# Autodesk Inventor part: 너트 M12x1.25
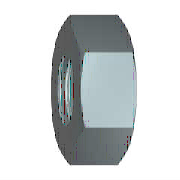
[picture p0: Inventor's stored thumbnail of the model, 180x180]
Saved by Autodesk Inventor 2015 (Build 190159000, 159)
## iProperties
IsCustomPart: 1
Created: 2012-02
Part Number: 너트 M12x1.25
Material: 강철, 연강
Description: 6각 너트
Document SubType Name: Modeling
Standard: KS B 1012
Designer: mduedu
Standards Organization: KS
Language: ko-KR
Size Designation: M12x1.25
Categories: <MemberInstance><Categories><Category DisplayName="조임쇠" InternalName="e4da775c-781d-43d5-af7c-5136215cf5a6" Mnemonic="FSTN"><Category DisplayName="너트" InternalN
Density: 1 g/cm^3
Appearance: 강철
Author: mduedu
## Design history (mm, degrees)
sketch "스케치1"
  geometry: L1 (-10.97, 0)-(-5.485, 9.5); L2 (-5.485, 9.5)-(5.485, 9.5); L3 (5.485, 9.5)-(10.97, 0); L4 (10.97, 0)-(5.485, -9.5); L5 (5.485, -9.5)-(-5.485, -9.5); L6 (-5.485, -9.5)-(-10.97, 0); 2 further points
  constraints: 12 end point, 1 coincident, 1 horizontal, 11 other
  dimensions: "d0" = 21.93931 distance of L3.end L1.start (= 1.1547 x SW)
extrude "본체" new body sketch "스케치1" distance "d1" = 10 (= KOH); taper "d2" = 0 deg
sketch "스케치2"
  geometry: L1 (0, 5.485)-(0, 10.97) reference; L2 (0, 10.97)-(10, 10.97) reference; L3 (10, 5.485)-(10, 10.97) reference; L4 (-2, 0)-(12, 0) reference; L5 (0.849, 10.97)-(0, 9.5); L6 (9.151, 10.97)-(10, 9.5)
  constraints: 4 end point, 4 point on line
  dimensions: "d3" = 30 deg angle of L1 L5 (= ANG1); "d4" = 30 deg angle of L3 L6 (= ANG2); "d5" = 19 diameter of L5.end L4 (= SW0); "d6" = 19 diameter of L6.end L4 (= SW01)
revolve "모따기1" sketch "스케치2" stored, may be unused: angle "d7" = 90 deg
sketch "스케치3"
  geometry: A1 r 9.5 centre (0, 0) between (-4.75, -8.227) and (4.75, -8.227) reference; 1 further point
  constraints: 1 coincident
hole "스레드" sketch "스케치3" at (0, 0) diameter "d25" = 10.647; stored, may be unused: countersink angle "d29" = 82 deg, drill point angle "d31" = 118 deg; dims "d26" = 6, "d27" = 4, "d28" = 2, "d30" = 8
workaxis "Work Axis1"
workplane "Work Plane1"
body "Solid1"
chamfer "모따기2" distance "d8" = 0.67658 (= -0.5 x GD1 + 0.5 x NND); stored, may be unused: angle "d9" = 30 deg, second distance "d40" = 0.67658 (= -0.5 x GD1 + 0.5 x NND)
chamfer "모따기3" distance "d10" = 0.67658 (= -0.5 x GD1 + 0.5 x NND); stored, may be unused: angle "d11" = 30 deg, second distance "d41" = 0.67658 (= -0.5 x GD1 + 0.5 x NND)
other parameters: "ANG1" = 30 deg [user parameter; used in 1 equation term], "ANG2" = 30 deg [user parameter; used in 1 equation term], "NND" = 12 [user parameter; used in 4 equation terms], "KOH" = 10 [user parameter; used in 1 equation term], "SW" = 19 [user parameter; used in 4 equation terms], "SW0" = 19 (= SW) [user parameter; used in 1 equation term], "SW01" = 19 (= SW) [user parameter; used in 1 equation term], "GD1" = 10.64684 (computed from THREADDIA, PTC, TOA) [user parameter; used in 4 equation terms], "d13" = 0, "d14" = 0, "d39" = 0, "d42" = 0, "GUL" = 0.67658 (= 0.541266 x PTC) [user parameter], "TPU" = 8 (computed from PTC) [user parameter], "THREADDIA" = 12 [user parameter; used in 1 equation term], "TOA" = 30 deg [user parameter; used in 1 equation term], "PTC" = 1.25 [user parameter; used in 4 equation terms], "E0" = 21.945 (= 1.155 x SW) [user parameter], "GAL" = 0.67658 (= 0.541266 x PTC) [user parameter]
